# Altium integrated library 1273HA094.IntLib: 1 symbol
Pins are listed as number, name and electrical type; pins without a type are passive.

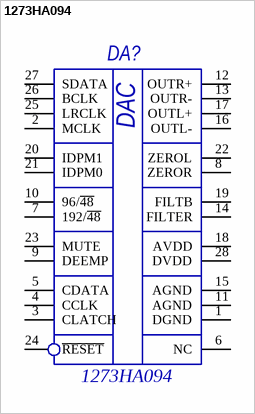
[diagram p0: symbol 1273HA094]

## 1273HA094
designator DA?
Manufacturer: АО"НИИЭТ"; Library Developer: Voronov   (aleksey.voronov.36@yandex.ru)
footprint 4119.28-1
pins: 1 DGND, 2 MCLK, 3 CLATCH, 4 CCLK, 5 CDATA, 6 NC, 7 192/~{48}, 8 ZEROR, 9 DEEMP, 10 96/~{48}, 11 AGND, 12 OUTR+, 13 OUTR-, 14 FILTER, 15 AGND, 16 OUTL-, 17 OUTL+, 18 AVDD, 19 FILTB, 20 IDPM1, 21 IDPM0, 22 ZEROL, 23 MUTE, 24 ~{RESET}, 25 LRCLK, 26 BCLK, 27 SDATA, 28 DVDD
